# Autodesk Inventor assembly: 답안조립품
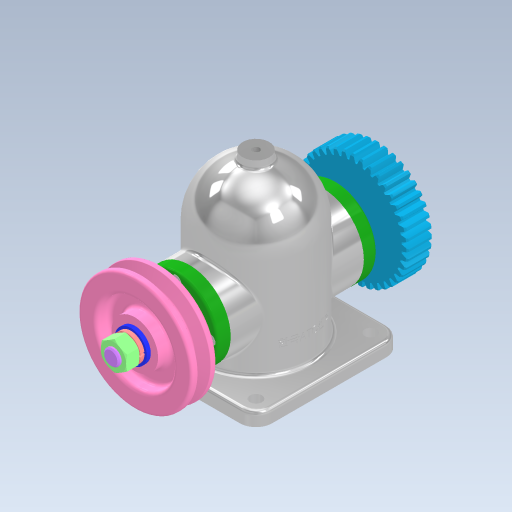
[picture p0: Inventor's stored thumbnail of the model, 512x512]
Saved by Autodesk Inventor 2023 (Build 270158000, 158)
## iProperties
Created: 2025-04
Part Number: 답안조립품
Document SubType Name: Assembly
Designer: Admin
Author: Admin
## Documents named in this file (14)
- C:\Users\Admin\Desktop\750406V1004\답안조립품.iam
- C:\Users\Admin\Desktop\750406V1004\본체.ipt
- C:\Users\Admin\Desktop\750406V1004\깊은 홈 볼 베어링 6203.ipt
- C:\Users\Admin\Desktop\750406V1004\축.ipt
- C:\Users\Admin\Desktop\750406V1004\커버.ipt
- C:\Users\Admin\Desktop\750406V1004\오일 실 26 38 8.ipt
- C:\Users\Admin\Desktop\750406V1004\6각 구멍붙이 볼트 M4x12.ipt
- C:\Users\Admin\Desktop\750406V1004\칼라.ipt
- C:\Users\Admin\Desktop\750406V1004\평와셔 M12.ipt
- C:\Users\Admin\Desktop\750406V1004\평행 키 5x5x12.ipt
- C:\Users\Admin\Desktop\750406V1004\스퍼기어.ipt
- C:\Users\Admin\Desktop\750406V1004\V 벨트 풀리.ipt
- C:\Users\Admin\Desktop\750406V1004\스프링 와셔 M12.ipt
- C:\Users\Admin\Desktop\750406V1004\6각 너트 M12x1.ipt
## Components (11 placed, 3 different names)
1. 6각 구멍붙이 볼트 M4x12:1
2. 6각 구멍붙이 볼트 M4x12:2
3. 6각 구멍붙이 볼트 M4x12:3
4. 6각 구멍붙이 볼트 M4x12:4
5. 6각 구멍붙이 볼트 M4x12:5
6. 6각 구멍붙이 볼트 M4x12:6
7. 6각 구멍붙이 볼트 M4x12:7
8. 6각 구멍붙이 볼트 M4x12:8
9. V 벨트 풀리:1
10. 6각 너트 M12x1:1
11. 6각 너트 M12x1:2
